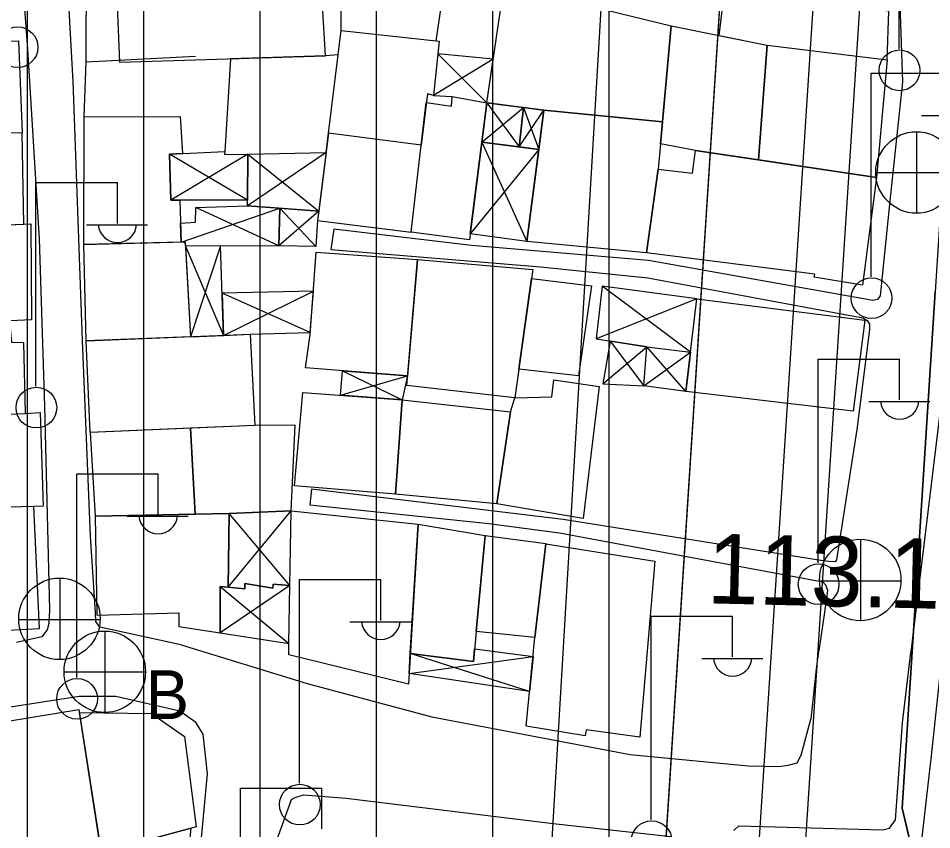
# Model space of a CAD drawing. Extents: x 417997 to 421451, y 4451742 to 4455216.
# Drawn here: x 419754.1 to 419832.6, y 4453026.6 to 4453096.3 of the extents above; entities that cross this region are included whole.
import ezdxf

# ---------------------------------------------------------------- set-up
doc = ezdxf.new("R2010")
doc.units = 0
for name, color, linetype in [('ADAKENARI', 7, 'Continuous'), ('B_Kapi', 7, 'Continuous'), ('B_Mesken', 7, 'Continuous'), ('B_Sundurma', 7, 'Continuous'), ('B_Teras', 7, 'Continuous'), ('KALDIRIM', 7, 'Continuous'), ('PL_EĞİTİM', 7, 'Continuous'), ('PL_KON_MEV_350', 7, 'Continuous'), ('S_Elektrik_Diregi', 7, 'Continuous'), ('S_Rogar_Kapagi', 7, 'Continuous'), ('S_Rogar_Kapagi_Buski', 7, 'Continuous'), ('Sinir_Duvar_tek_tarafa_ait', 7, 'Continuous'), ('SN_KENTSEL_DONUSUM', 7, 'Continuous'), ('TR_ORTAYOGUNKONUT', 7, 'Continuous'), ('Y_Yol_Kotu', 7, 'Continuous'), ('Yol_Sose', 7, 'Continuous')]:
    doc.layers.add(name, color=color, linetype=linetype)

msp = doc.modelspace()

# ---------------------------------------------------------------- linework, layer by layer
at = {"layer": 'ADAKENARI'}
for p, q in [((419816.158, 4453124.471), (419809.709, 4453024.608)), ((419816.158, 4453124.471), (419809.709, 4453024.608)), ((419830.093, 4453028.46), (419832.939, 4453072.833)), ((419830.093, 4453028.46), (419832.939, 4453072.833)), ((419832.318, 4453019.167), (419830.093, 4453028.46)), ((419832.318, 4453019.167), (419830.093, 4453028.46))]:
    msp.add_line(p, q, dxfattribs=at)
at = {"layer": 'B_Kapi'}
msp.add_lwpolyline([(419831.71, 4453024.97), (419832.631, 4453032.94)], dxfattribs=at)
at = {"layer": 'B_Mesken'}
for points in [[(419815.853, 4453104.327), (419815.808, 4453103.417), (419814.754, 4453103.532), (419814.706, 4453102.682), (419814.011, 4453102.677), (419813.862, 4453099.665), (419815.778, 4453099.339), (419815.682, 4453098.865), (419814.819, 4453098.865), (419814.359, 4453094.857), (419818.503, 4453094.019), (419828.807, 4453092.756), (419828.965, 4453096.944), (419827.949, 4453097.068), (419827.906, 4453099.158), (419829.006, 4453099.102), (419828.732, 4453101.785), (419827.991, 4453101.879), (419828.03, 4453102.648), (419824.406, 4453103.014), (419824.441, 4453103.311)], [(419780.553, 4453093.099), (419780.029, 4453101.85), (419762.499, 4453100.952), (419762.828, 4453092.571)], [(419798.119, 4453098.713), (419800.873, 4453098.316), (419803.43, 4453097.971), (419803.421, 4453097.336), (419810.253, 4453095.687), (419809.507, 4453087.427), (419799.319, 4453088.426), (419794.409, 4453089.08), (419795.846, 4453098.823)], [(419780.812, 4453086.46), (419781.886, 4453095.279), (419790.321, 4453094.363), (419789.816, 4453089.705), (419789.294, 4453089.852), (419788.77, 4453085.422)], [(419817.762, 4453084.169), (419812.342, 4453084.978), (419809.339, 4453085.561), (419810.253, 4453095.687), (419818.503, 4453094.019)], [(419747.686, 4453086.332), (419747.467, 4453088.73), (419746.931, 4453089.022), (419746.605, 4453094.09), (419753.497, 4453094.358), (419754.164, 4453094.403), (419754.474, 4453086.499)], [(419817.762, 4453084.169), (419818.503, 4453094.019), (419828.807, 4453092.756), (419827.897, 4453082.656)], [(419780.602, 4453084.806), (419780.812, 4453086.46), (419781.633, 4453093.198), (419780.553, 4453093.099), (419772.369, 4453092.855), (419771.889, 4453084.874), (419771.871, 4453084.625), (419773.854, 4453084.67)], [(419787.912, 4453077.963), (419788.77, 4453085.422), (419789.206, 4453089.106), (419791.378, 4453088.783), (419791.437, 4453089.617), (419794.409, 4453089.08), (419792.916, 4453077.293)], [(419808.127, 4453076.174), (419797.841, 4453077.161), (419799.319, 4453088.426), (419809.507, 4453087.427), (419809.339, 4453085.561), (419809.129, 4453083.358)], [(419759.761, 4453076.897), (419759.812, 4453087.863), (419768.047, 4453087.888), (419768.239, 4453084.712), (419767.149, 4453084.663), (419767.242, 4453080.698), (419768.017, 4453080.7), (419768.138, 4453077.106)], [(419754.618, 4453078.64), (419754.474, 4453086.499), (419745.681, 4453086.283), (419744.9, 4453078.237)], [(419780.812, 4453086.46), (419779.86, 4453078.949), (419787.912, 4453077.963), (419788.77, 4453085.422)], [(419808.127, 4453076.174), (419809.129, 4453083.358), (419812.07, 4453083.025), (419812.342, 4453084.978), (419827.897, 4453082.656), (419826.702, 4453073.393), (419822.546, 4453074.096), (419822.597, 4453074.35)], [(419738.392, 4453077.966), (419755.221, 4453078.665), (419755.276, 4453070.414), (419742.593, 4453069.828), (419742.529, 4453071.142), (419738.771, 4453070.801), (419738.712, 4453073.588)], [(419768.491, 4453077.115), (419768.946, 4453068.969), (419759.969, 4453068.606), (419759.761, 4453076.897)], [(419787.602, 4453065.616), (419778.836, 4453066.288), (419779.213, 4453069.165), (419779.513, 4453073.082), (419779.752, 4453076.227), (419788.462, 4453075.614)], [(419787.53, 4453064.777), (419788.462, 4453075.614), (419798.357, 4453074.761), (419796.806, 4453063.706)], [(419798.246, 4453073.976), (419803.41, 4453073.335), (419802.283, 4453065.6), (419797.151, 4453066.17)], [(419811.499, 4453064.275), (419812.453, 4453072.224), (419826.896, 4453070.384), (419825.892, 4453062.573)], [(419742.593, 4453069.828), (419741.841, 4453069.829), (419741.914, 4453068.249), (419740.734, 4453068.156), (419740.987, 4453063.802), (419742.07, 4453063.976), (419742.208, 4453061.921), (419743.721, 4453061.981), (419754.763, 4453062.376), (419754.622, 4453068.44), (419753.579, 4453068.46), (419753.421, 4453070.328)], [(419774.069, 4453069.176), (419774.463, 4453061.333), (419760.319, 4453060.738), (419759.969, 4453068.606)], [(419796.45, 4453062.512), (419796.806, 4453063.706), (419800.007, 4453063.797), (419800.174, 4453065.255), (419804.067, 4453064.682), (419802.68, 4453053.351), (419795.257, 4453054.608)], [(419787.122, 4453063.551), (419786.547, 4453055.447), (419777.891, 4453056.154), (419778.593, 4453064.177)], [(419787.122, 4453063.551), (419796.45, 4453062.512), (419795.257, 4453054.608), (419786.547, 4453055.447)], [(419743.908, 4453053.982), (419739.563, 4453053.761), (419739.134, 4453062.111), (419742.184, 4453062.284), (419742.208, 4453061.921), (419743.71, 4453061.981), (419754.763, 4453062.376), (419756.016, 4453062.451), (419756.276, 4453054.404), (419755.465, 4453054.37), (419746.749, 4453054.129)], [(419768.929, 4453061.1), (419769.343, 4453053.709), (419772.267, 4453053.764), (419777.579, 4453054.003), (419777.939, 4453061.378), (419774.463, 4453061.333)], [(419769.343, 4453053.709), (419768.929, 4453061.1), (419760.319, 4453060.738), (419760.748, 4453053.548)], [(419746.749, 4453054.129), (419747.279, 4453043.437), (419755.951, 4453043.882), (419755.465, 4453054.37)], [(419760.748, 4453053.548), (419760.9, 4453045.028), (419767.943, 4453045.232), (419767.938, 4453044.07), (419771.48, 4453043.522), (419771.491, 4453047.513), (419772.191, 4453047.44), (419772.267, 4453053.764)], [(419777.579, 4453054.003), (419788.509, 4453052.873), (419787.665, 4453039.097), (419777.397, 4453041.629), (419777.378, 4453042.61), (419777.466, 4453047.595)], [(419788.509, 4453052.873), (419794.259, 4453051.896), (419793.484, 4453043.645), (419793.272, 4453041.057), (419787.828, 4453041.756)], [(419794.259, 4453051.896), (419799.492, 4453051.185), (419798.538, 4453043.118), (419793.484, 4453043.645)], [(419799.492, 4453051.178), (419808.846, 4453049.694), (419807.547, 4453034.546), (419802.951, 4453035.178), (419802.86, 4453034.656), (419797.783, 4453035.499), (419798.538, 4453043.121)], [(419749.027, 4453035.25), (419759.352, 4453036.939), (419761.307, 4453024.33), (419751.873, 4453021.983)], [(419759.392, 4453036.683), (419765.588, 4453036.601), (419768.41, 4453034.602), (419769.44, 4453026.853), (419761.26, 4453024.635)], [(419768.955, 4453026.721), (419767.685, 4453013.936), (419761.317, 4453012), (419760.744, 4453024.19), (419761.307, 4453024.33), (419761.26, 4453024.635)]]:
    msp.add_lwpolyline(points, close=True, dxfattribs=at)
at = {"layer": 'B_Sundurma'}
for p, q in [((419794.963, 4453092.834), (419789.816, 4453089.705)), ((419794.409, 4453089.08), (419790.203, 4453093.276)), ((419794.409, 4453089.08), (419797.178, 4453085.287)), ((419793.98, 4453085.691), (419797.549, 4453088.662)), ((419797.178, 4453085.287), (419799.319, 4453088.426)), ((419797.549, 4453088.662), (419798.879, 4453085.072)), ((419793.98, 4453085.691), (419797.841, 4453077.161)), ((419780.602, 4453084.806), (419773.838, 4453080.224)), ((419798.879, 4453085.072), (419792.981, 4453077.808)), ((419773.828, 4453080.719), (419767.149, 4453084.663)), ((419773.854, 4453084.67), (419767.242, 4453080.698)), ((419773.854, 4453084.67), (419779.962, 4453079.754)), ((419776.537, 4453076.794), (419769.389, 4453080.089)), ((419768.138, 4453077.106), (419776.61, 4453080.011)), ((419779.962, 4453079.754), (419776.537, 4453076.794)), ((419779.709, 4453076.734), (419776.61, 4453080.011)), ((419768.511, 4453076.757), (419771.774, 4453069.083)), ((419771.512, 4453076.771), (419768.946, 4453068.969)), ((419811.904, 4453067.652), (419804.321, 4453073.321)), ((419779.225, 4453069.328), (419771.65, 4453072.726)), ((419771.774, 4453069.083), (419779.498, 4453072.896)), ((419812.453, 4453072.224), (419803.809, 4453068.788)), ((419804.997, 4453068.599), (419807.901, 4453064.762)), ((419804.377, 4453064.918), (419808.157, 4453068.096)), ((419807.901, 4453064.762), (419811.904, 4453067.652)), ((419811.499, 4453064.275), (419808.157, 4453068.096)), ((419782.007, 4453066.045), (419787.122, 4453063.551)), ((419781.836, 4453063.939), (419787.602, 4453065.616)), ((419772.191, 4453047.44), (419777.579, 4453054.003)), ((419777.466, 4453047.595), (419772.267, 4453053.764)), ((419777.466, 4453047.595), (419771.48, 4453043.522)), ((419771.491, 4453047.513), (419777.378, 4453042.61)), ((419798.079, 4453038.484), (419787.828, 4453041.756)), ((419787.721, 4453040.013), (419798.377, 4453041.49))]:
    msp.add_line(p, q, dxfattribs=at)
for points in [[(419794.409, 4453089.08), (419794.963, 4453092.834), (419790.203, 4453093.276), (419789.816, 4453089.705), (419791.437, 4453089.617)], [(419793.98, 4453085.691), (419794.409, 4453089.08), (419797.549, 4453088.662), (419797.178, 4453085.287)], [(419797.178, 4453085.287), (419797.549, 4453088.662), (419799.319, 4453088.426), (419798.879, 4453085.072)], [(419793.98, 4453085.691), (419798.879, 4453085.072), (419797.841, 4453077.161), (419792.981, 4453077.808)], [(419773.854, 4453084.67), (419773.828, 4453080.719), (419767.242, 4453080.698), (419767.149, 4453084.663), (419771.889, 4453084.874), (419771.871, 4453084.625)], [(419773.854, 4453084.67), (419780.602, 4453084.806), (419779.962, 4453079.754), (419773.838, 4453080.224), (419773.828, 4453080.719)], [(419776.537, 4453076.794), (419768.511, 4453076.757), (419768.491, 4453077.115), (419768.138, 4453077.106), (419768.083, 4453078.719), (419769.364, 4453078.813), (419769.389, 4453080.089), (419773.838, 4453080.224), (419776.61, 4453080.011)], [(419779.962, 4453079.754), (419779.86, 4453078.949), (419779.709, 4453076.734), (419776.537, 4453076.794), (419776.61, 4453080.011)], [(419771.512, 4453076.771), (419768.511, 4453076.757), (419768.946, 4453068.969), (419771.774, 4453069.083)], [(419811.904, 4453067.652), (419812.453, 4453072.224), (419804.321, 4453073.321), (419803.809, 4453068.788), (419808.157, 4453068.096)], [(419771.774, 4453069.083), (419774.069, 4453069.176), (419779.225, 4453069.328), (419779.498, 4453072.896), (419771.65, 4453072.726)], [(419804.997, 4453068.599), (419804.377, 4453064.918), (419807.901, 4453064.762), (419808.157, 4453068.096)], [(419811.499, 4453064.275), (419807.901, 4453064.762), (419808.157, 4453068.096), (419811.904, 4453067.652)], [(419781.836, 4453063.939), (419782.007, 4453066.045), (419787.602, 4453065.616), (419787.122, 4453063.551)], [(419772.191, 4453047.44), (419773.596, 4453047.293), (419773.622, 4453047.77), (419776.014, 4453047.36), (419776.052, 4453047.696), (419777.466, 4453047.595), (419777.579, 4453054.003), (419772.267, 4453053.764)], [(419777.466, 4453047.595), (419776.052, 4453047.696), (419776.014, 4453047.36), (419773.622, 4453047.77), (419773.596, 4453047.293), (419771.491, 4453047.513), (419771.48, 4453043.522), (419777.378, 4453042.61)], [(419798.079, 4453038.484), (419787.721, 4453040.013), (419787.828, 4453041.756), (419793.272, 4453041.057), (419793.361, 4453042.143), (419798.377, 4453041.49)]]:
    msp.add_lwpolyline(points, close=True, dxfattribs=at)
at = {"layer": 'B_Teras'}
msp.add_lwpolyline([(419743.908, 4453053.982), (419743.71, 4453061.981), (419754.763, 4453062.376), (419756.016, 4453062.451), (419756.276, 4453054.404), (419755.465, 4453054.37), (419746.749, 4453054.129)], close=True, dxfattribs=at)
at = {"layer": 'KALDIRIM'}
for p, q in [((419830.985, 4453229.943), (419817.752, 4453025.012)), ((419830.985, 4453229.943), (419817.752, 4453025.012)), ((419834.985, 4453229.812), (419821.75, 4453024.849)), ((419834.985, 4453229.812), (419821.75, 4453024.849))]:
    msp.add_line(p, q, dxfattribs=at)
at = {"layer": 'PL_EĞİTİM'}
msp.add_lwpolyline([(419833.483, 4453081.316), (419832.939, 4453072.833), (419830.093, 4453028.46), (419832.318, 4453019.167), (419835.641, 4453013.55), (419842.714, 4453007.124), (419897.31, 4452981.528), (419905.437, 4452977.718), (419912.059, 4453068.004), (419912.691, 4453076.44), (419833.483, 4453081.316)], dxfattribs=at)
msp.add_lwpolyline([(419833.483, 4453081.316), (419832.939, 4453072.833), (419830.093, 4453028.46), (419832.318, 4453019.167), (419835.641, 4453013.55), (419842.714, 4453007.124), (419897.31, 4452981.528), (419905.437, 4452977.718), (419912.059, 4453068.004), (419912.691, 4453076.44), (419833.483, 4453081.316)], dxfattribs=at)
at = {"layer": 'PL_KON_MEV_350'}
msp.add_lwpolyline([(419823.627, 4453240.148), (419822.565, 4453223.702), (419795.483, 4453226.221), (419799.027, 4453156.869), (419756.504, 4453159.4), (419758.023, 4453124.471), (419816.158, 4453124.471), (419809.709, 4453024.608), (419799.347, 4453012.271), (419707.401, 4453034.871), (419706.895, 4453052.588), (419682.596, 4453052.082), (419684.115, 4453033.858), (419707.401, 4453034.871), (419799.347, 4453012.271), (419560.39, 4452954.317), (419542.266, 4452957.376), (419468.571, 4453004.865), (419464.929, 4453019.074), (419512.36, 4453106.601), (419622.453, 4453235.699), (419667.916, 4453224.196), (419710.945, 4453222.677), (419709.932, 4453261.656)], dxfattribs=at)
at = {"layer": 'S_Elektrik_Diregi'}
for p, q in [((419829.835, 4453093.701), (419829.835, 4453111.201)), ((419827.436, 4453074.119), (419827.436, 4453091.619)), ((419827.436, 4453091.619), (419834.436, 4453091.619)), ((419831.776, 4453087.979), (419837.026, 4453087.979)), ((419755.658, 4453064.713), (419755.658, 4453082.213)), ((419755.658, 4453082.213), (419762.658, 4453082.213)), ((419762.658, 4453078.713), (419762.658, 4453082.213)), ((419759.998, 4453078.573), (419765.248, 4453078.573)), ((419822.886, 4453049.531), (419822.886, 4453067.032)), ((419822.886, 4453067.032), (419829.886, 4453067.032)), ((419829.886, 4453063.532), (419829.886, 4453067.032)), ((419827.226, 4453063.391), (419832.476, 4453063.391)), ((419759.157, 4453039.685), (419759.157, 4453057.185)), ((419759.157, 4453057.185), (419766.157, 4453057.185)), ((419766.157, 4453053.685), (419766.157, 4453057.185)), ((419763.497, 4453053.545), (419768.747, 4453053.545)), ((419778.301, 4453030.593), (419778.301, 4453048.093)), ((419778.301, 4453048.093), (419785.301, 4453048.093)), ((419785.301, 4453044.593), (419785.301, 4453048.093)), ((419808.532, 4453027.452), (419808.532, 4453044.952)), ((419808.532, 4453044.952), (419815.532, 4453044.952)), ((419815.532, 4453041.452), (419815.532, 4453044.952)), ((419782.641, 4453044.453), (419787.891, 4453044.453)), ((419812.872, 4453041.312), (419818.122, 4453041.312)), ((419773.235, 4453012.669), (419773.235, 4453030.17)), ((419773.235, 4453030.17), (419780.235, 4453030.17)), ((419780.235, 4453026.67), (419780.235, 4453030.17))]:
    msp.add_line(p, q, dxfattribs=at)
for centre in [(419754.08, 4453093.846), (419829.871, 4453091.865), (419827.472, 4453072.284), (419755.694, 4453062.877), (419822.922, 4453047.696), (419759.193, 4453037.849), (419778.337, 4453028.757), (419808.568, 4453025.617)]:
    msp.add_circle(centre, 1.75, dxfattribs=at)
for centre in [(419762.659, 4453078.726), (419829.887, 4453063.544), (419766.158, 4453053.698), (419785.302, 4453044.606), (419815.533, 4453041.465)]:
    msp.add_arc(centre, 1.658, 184.83843, 355.14641, dxfattribs=at)
at = {"layer": 'S_Rogar_Kapagi'}
for p, q in [((419826.549, 4453044.531), (419826.549, 4453051.531)), ((419757.731, 4453041.195), (419757.731, 4453048.195)), ((419822.979, 4453047.996), (419829.979, 4453047.996)), ((419754.161, 4453044.66), (419761.161, 4453044.66))]:
    msp.add_line(p, q, dxfattribs=at)
for centre in [(419826.495, 4453048.059), (419757.678, 4453044.724)]:
    msp.add_circle(centre, 3.5, dxfattribs=at)
at = {"layer": 'S_Rogar_Kapagi_Buski'}
for p, q in [((419831.332, 4453086.584), (419831.332, 4453079.584)), ((419827.832, 4453083.084), (419834.832, 4453083.084)), ((419761.573, 4453043.674), (419761.573, 4453036.674)), ((419758.073, 4453040.174), (419765.073, 4453040.174))]:
    msp.add_line(p, q, dxfattribs=at)
for centre in [(419831.332, 4453083.084), (419761.573, 4453040.174)]:
    msp.add_circle(centre, 3.5, dxfattribs=at)
at = {"layer": 'Sinir_Duvar_tek_tarafa_ait'}
for points in [[(419781.886, 4453095.279), (419781.746, 4453118.522), (419783.506, 4453118.55)], [(419759.985, 4453092.585), (419760.014, 4453100.729)], [(419790.707, 4453099.074), (419790.037, 4453094.394)], [(419759.812, 4453087.863), (419759.985, 4453092.585), (419769.36, 4453093.075)], [(419832.631, 4453032.94), (419833.562, 4453041.802)]]:
    msp.add_lwpolyline(points, dxfattribs=at)
at = {"layer": 'SN_KENTSEL_DONUSUM'}
msp.add_line((419799.082, 4453009.731), (419813.436, 4453253.023), dxfattribs=at)
msp.add_line((419799.082, 4453009.731), (419813.436, 4453253.023), dxfattribs=at)
at = {"layer": 'TR_ORTAYOGUNKONUT'}
for p, q in [((419754.929, 4453001.499), (419754.929, 4453364.973)), ((419754.929, 4453001.499), (419754.929, 4453364.973)), ((419764.929, 4453003.924), (419764.929, 4453124.471)), ((419764.929, 4453003.924), (419764.929, 4453124.471)), ((419774.929, 4453006.349), (419774.929, 4453124.471)), ((419774.929, 4453006.349), (419774.929, 4453124.471)), ((419784.929, 4453008.775), (419784.929, 4453124.471)), ((419784.929, 4453008.775), (419784.929, 4453124.471)), ((419794.929, 4453011.2), (419794.929, 4453124.471)), ((419794.929, 4453011.2), (419794.929, 4453124.471)), ((419804.929, 4453018.917), (419804.929, 4453124.471)), ((419804.929, 4453018.917), (419804.929, 4453124.471))]:
    msp.add_line(p, q, dxfattribs=at)
at = {"layer": 'Yol_Sose'}
for points in [[(419767.865, 4453042.555), (419761.154, 4453044.014), (419760.794, 4453044.5), (419760.772, 4453045.258), (419760.359, 4453051.835), (419759.659, 4453068.639), (419758.843, 4453090.905), (419757.423, 4453116.602), (419756.873, 4453136.835), (419756.012, 4453156.591), (419754.657, 4453174.547)], [(419719.326, 4453115.592), (419719.455, 4453116.667), (419719.775, 4453117.048), (419734.051, 4453118.335), (419752.745, 4453119.11), (419753.114, 4453119.032), (419753.472, 4453118.695), (419753.616, 4453118.222), (419753.98, 4453106.434), (419754.944, 4453093.686), (419755.946, 4453077.378), (419756.38, 4453062.989), (419756.83, 4453045.49), (419756.769, 4453044.322), (419756.615, 4453043.773), (419756.165, 4453043.182), (419753.99, 4453042.702)], [(419829.758, 4453101.71), (419830.121, 4453090.876), (419829.04, 4453080.643), (419828.207, 4453072.495), (419827.98, 4453072.169), (419827.578, 4453072.079), (419808.287, 4453075.526), (419793.094, 4453076.821), (419781.254, 4453078.21), (419780.997, 4453076.48), (419799.011, 4453074.966), (419808.237, 4453074.021), (419826.724, 4453070.579), (419827.083, 4453070.351), (419827.308, 4453070.063), (419827.302, 4453069.579), (419826.199, 4453060.998), (419824.451, 4453049.798), (419824.33, 4453049.629), (419823.801, 4453049.663), (419823.118, 4453049.742), (419800.969, 4453053.267), (419779.33, 4453055.878), (419779.187, 4453054.509), (419794.565, 4453052.922), (419800.643, 4453052.108), (419823.29, 4453047.916), (419823.51, 4453047.635), (419823.691, 4453047.2), (419823.585, 4453046.463), (419822.928, 4453041.974)], [(419830.866, 4453041.89), (419833.623, 4453064.518), (419834.961, 4453079.203)], [(419768.141, 4453042.495), (419767.865, 4453042.555)], [(419768.141, 4453042.495), (419778.956, 4453039.18), (419789.678, 4453036.306), (419806.716, 4453033.054), (419816.877, 4453032.093), (419819.508, 4453032.042), (419820.314, 4453032.146), (419821.07, 4453032.347), (419821.433, 4453032.999), (419822.257, 4453036.116)], [(419822.919, 4453041.915), (419822.7, 4453040.421), (419822.257, 4453036.116)], [(419822.928, 4453041.974), (419822.919, 4453041.915)], [(419830.121, 4453035.779), (419830.858, 4453041.831)], [(419830.858, 4453041.831), (419830.866, 4453041.89)], [(419696.262, 4452981.237), (419697.008, 4452981.323), (419700.842, 4452982.163), (419713.345, 4452985.766), (419737.756, 4452991.94), (419766.909, 4452999.339), (419767.13, 4452999.551), (419767.273, 4453000.018), (419768.65, 4453012.751), (419770.401, 4453031.417), (419770.028, 4453034.805), (419769.403, 4453035.817), (419768.035, 4453036.794), (419762.516, 4453038.039), (419759.382, 4453038.045), (419731.471, 4453033.737), (419716.691, 4453030.735), (419694.51, 4453025.791)], [(419815.641, 4453026.541), (419816.066, 4453026.929), (419828.453, 4453026.596), (419829.005, 4453026.725), (419829.541, 4453027.443), (419830.121, 4453035.779)], [(419797.885, 4452986.916), (419770.749, 4452993.719), (419770.468, 4452994.106), (419770.256, 4452994.722), (419770.165, 4452995.499), (419771.602, 4453004.575), (419773.097, 4453013.031), (419776.363, 4453025.691), (419777.627, 4453029.197), (419777.933, 4453029.373), (419778.661, 4453029.594), (419782.332, 4453029.307), (419800.106, 4453027.129), (419810.214, 4453026.031), (419810.457, 4453025.735), (419810.652, 4453025.494), (419810.774, 4453024.943), (419810.835, 4453024.256), (419809.537, 4453016.205)]]:
    msp.add_lwpolyline(points, dxfattribs=at)

# ---------------------------------------------------------------- texts
at = {"layer": 'S_Rogar_Kapagi_Buski'}
msp.add_text('B', height=4.2, dxfattribs=at).set_placement((419765.073, 4453036.11))
at = {"layer": 'Y_Yol_Kotu'}
msp.add_text('113.17 ', height=6, rotation=358.64456, dxfattribs=at).set_placement((419813.275, 4453046.061))

doc.saveas('drawing.dxf')
